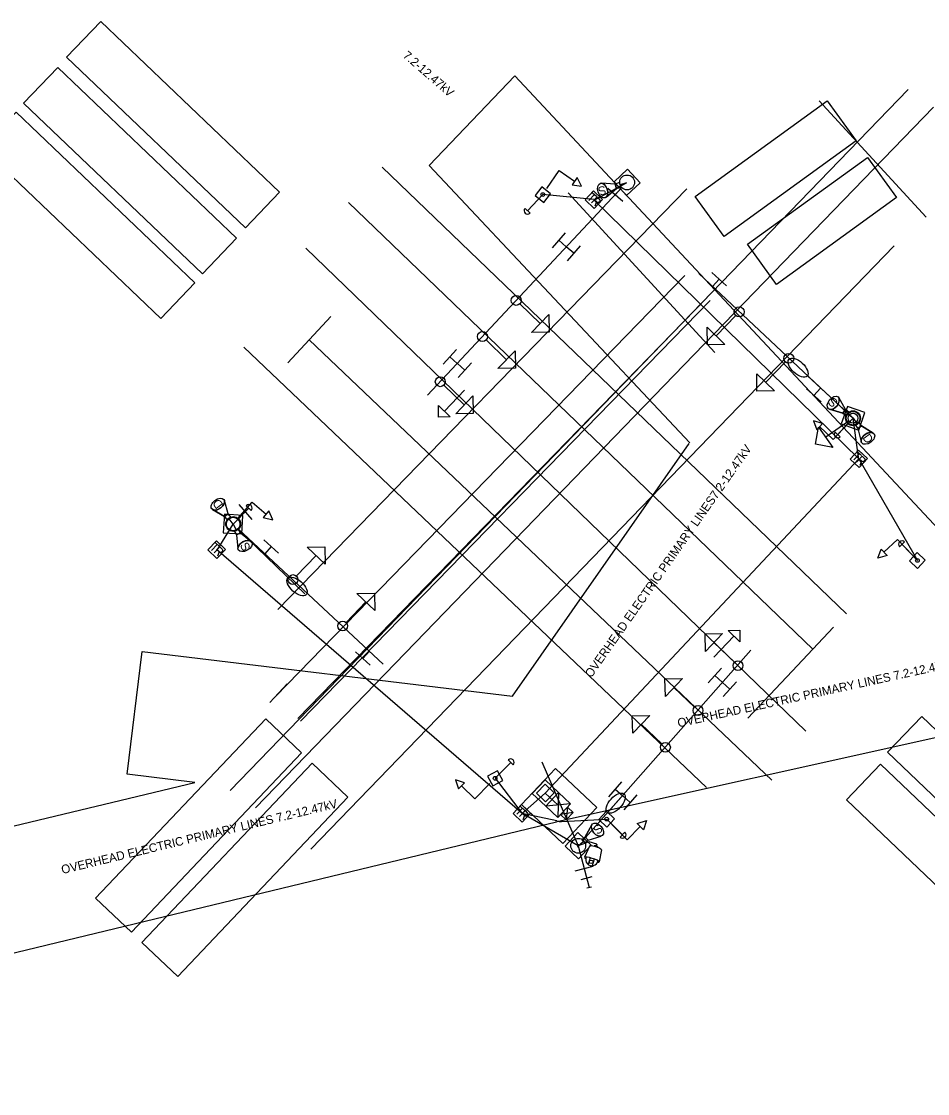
# Model space of a CAD drawing. Extents: x 1481246 to 1481610, y 378112 to 378300.
# Drawn here: x 1481367.5 to 1481514.1, y 378126.6 to 378300 of the extents above; entities that cross this region are included whole.
import ezdxf

# ---------------------------------------------------------------- set-up
doc = ezdxf.new("R2010")
doc.units = 0
for name, color, linetype in [('Default', 7, 'Continuous'), ('DR_X_Cells', 7, 'Continuous'), ('GK_Visualization', 7, 'Continuous'), ('PM_X_Cells', 7, 'Continuous'), ('RD_X_Cells', 7, 'Continuous'), ('SG_X_Poles', 7, 'Continuous'), ('SN_X_Private', 7, 'Continuous'), ('SV_X_Random_Point', 7, 'Continuous'), ('SV_X_Shot_Marker', 7, 'Continuous'), ('SV_X_Text_Elevation', 7, 'Continuous'), ('UT_X_Electric_Cells', 7, 'Continuous'), ('UT_X_Gas_Cells', 7, 'Continuous'), ('UT_X_Misc_Cells', 7, 'Continuous'), ('UT_X_Sanitary_Cells', 7, 'Continuous'), ('UT_X_Telecom_Cells', 7, 'Continuous'), ('UT_X_Unknown_Cells', 7, 'Continuous'), ('UT_X_Water_Cells', 7, 'Continuous')]:
    doc.layers.add(name, color=color, linetype=linetype)

msp = doc.modelspace()

# ---------------------------------------------------------------- linework, layer by layer
at = {"layer": 'Default'}
msp.add_line((1481410.48, 378192.83), (1481407.68, 378189.84), dxfattribs=at)
at = {"layer": 'GK_Visualization'}
for points in [[(1481465.41, 378271.81), (1481467.61, 378273.85), (1481465.57, 378276.05), (1481463.37, 378274.01)], [(1481451.99, 378270.7), (1481453.11, 378272.11), (1481451.7, 378273.23), (1481450.58, 378271.82)], [(1481500.13, 378234.89), (1481502.96, 378233.89), (1481503.96, 378236.72), (1481501.13, 378237.72)], [(1481400.14, 378217.29), (1481403.14, 378217.09), (1481403.33, 378220.09), (1481400.34, 378220.28)], [(1481512.5, 378211.52), (1481513.74, 378212.83), (1481512.44, 378214.07), (1481511.2, 378212.76)], [(1481443.78, 378176.34), (1481445.35, 378177.21), (1481444.49, 378178.79), (1481442.91, 378177.92)], [(1481462.22, 378169.69), (1481463.45, 378171), (1481462.14, 378172.24), (1481460.91, 378170.93)], [(1481457.64, 378164.54), (1481459.69, 378166.73), (1481457.5, 378168.78), (1481455.45, 378166.6)]]:
    msp.add_lwpolyline(points, close=True, dxfattribs=at)
for centre, radius in [((1481465.49, 378273.93), 1.2), ((1481451.84, 378271.97), 0.3), ((1481502.04, 378235.8), 1.2), ((1481401.74, 378218.69), 1.2), ((1481512.47, 378212.8), 0.3), ((1481444.13, 378177.57), 0.3), ((1481462.18, 378170.97), 0.3), ((1481457.57, 378166.66), 1.2)]:
    msp.add_circle(centre, radius, dxfattribs=at)
at = {"layer": 'PM_X_Cells'}
for p, q in [((1481464.77, 378270.86), (1481462.35, 378272.96)), ((1481463.56, 378271.91), (1481464.61, 378273.12)), ((1481453.39, 378263.37), (1481455.49, 378265.78)), ((1481454.44, 378264.58), (1481455.65, 378263.53)), ((1481456.86, 378262.48), (1481455.65, 378263.53)), ((1481457.91, 378263.68), (1481455.81, 378261.27)), ((1481479.19, 378259.36), (1481481.56, 378257.22)), ((1481480.37, 378258.29), (1481479.3, 378257.1)), ((1481435.72, 378244.55), (1481437.86, 378246.93)), ((1481436.79, 378245.74), (1481437.98, 378244.67)), ((1481439.22, 378243.55), (1481438.03, 378244.63)), ((1481440.29, 378244.74), (1481438.15, 378242.37)), ((1481496.91, 378238.43), (1481494.5, 378240.53)), ((1481495.71, 378239.48), (1481496.76, 378240.68)), ((1481402.68, 378221.85), (1481404.77, 378219.43)), ((1481403.73, 378220.64), (1481402.52, 378219.6)), ((1481406.72, 378216.11), (1481409.1, 378213.97)), ((1481407.91, 378215.04), (1481406.84, 378213.86)), ((1481423.91, 378195.89), (1481421.53, 378198.03)), ((1481422.72, 378196.96), (1481423.79, 378198.15)), ((1481478.62, 378193.01), (1481480.76, 378195.39)), ((1481479.69, 378194.2), (1481480.88, 378193.13)), ((1481482.11, 378191.98), (1481480.94, 378193.07)), ((1481483.2, 378193.15), (1481481.02, 378190.81)), ((1481462.51, 378174.58), (1481464.61, 378177)), ((1481463.56, 378175.79), (1481464.77, 378174.74)), ((1481465.99, 378173.68), (1481464.78, 378174.73)), ((1481467.04, 378174.89), (1481464.94, 378172.48))]:
    msp.add_line(p, q, dxfattribs=at)
at = {"layer": 'RD_X_Cells'}
for p, q in [((1481460.17, 378271.05), (1481465.38, 378273.87)), ((1481460.11, 378271.15), (1481451.84, 378271.97)), ((1481502.97, 378229.22), (1481460.09, 378271.13)), ((1481502.99, 378229.08), (1481502.04, 378235.8)), ((1481452.25, 378175.19), (1481502.99, 378229.24)), ((1481502.99, 378229.24), (1481512.47, 378212.8)), ((1481399.15, 378214.48), (1481401.74, 378218.69)), ((1481448.51, 378171.87), (1481399.06, 378214.55)), ((1481444.13, 378177.57), (1481448.52, 378171.87)), ((1481448.51, 378171.87), (1481452.25, 378175.19)), ((1481452.25, 378175.19), (1481454.31, 378173.24)), ((1481457.57, 378166.66), (1481448.45, 378171.91)), ((1481454.11, 378170.67), (1481448.52, 378171.87)), ((1481454.88, 378170.6), (1481462.18, 378170.97))]:
    msp.add_line(p, q, dxfattribs=at)
msp.add_arc((1481454.74, 378173.6), 3, 257.9002, 272.8324, dxfattribs=at)
at = {"layer": 'SG_X_Poles'}
for p, q in [((1481454.37, 378175.25), (1481454.25, 378171.24)), ((1481456.31, 378173.42), (1481452.31, 378173.07)), ((1481455.83, 378172.91), (1481455.63, 378170.88)), ((1481456.74, 378172.06), (1481454.72, 378171.74))]:
    msp.add_line(p, q, dxfattribs=at)
for points in [[(1481453.91, 378179.13), (1481448.41, 378173.32), (1481455.07, 378167.02), (1481460.57, 378172.83)], [(1481452.2, 378177.31), (1481450.13, 378175.13), (1481452.31, 378173.07), (1481454.37, 378175.25)], [(1481452.21, 378176.6), (1481450.84, 378175.15), (1481452.29, 378173.78), (1481453.67, 378175.23)], [(1481454.37, 378175.25), (1481456.31, 378173.42), (1481454.25, 378171.24), (1481452.31, 378173.07)], [(1481455.83, 378172.91), (1481456.74, 378172.06), (1481455.63, 378170.88), (1481454.72, 378171.74)]]:
    msp.add_lwpolyline(points, close=True, dxfattribs=at)
at = {"layer": 'SN_X_Private'}
for p, q in [((1481451.84, 378271.97), (1481451.84, 378271.97)), ((1481448.12, 378254.3), (1481451.43, 378251.11)), ((1481483.07, 378252.42), (1481479.87, 378249.12)), ((1481442.66, 378248.45), (1481445.97, 378245.26)), ((1481491.09, 378244.9), (1481487.89, 378241.6)), ((1481435.83, 378241.15), (1481439.14, 378237.96)), ((1481439.17, 378240.31), (1481435.91, 378236.93)), ((1481501.39, 378235.35), (1481497.62, 378232.72)), ((1481502.04, 378235.8), (1481502.04, 378235.8)), ((1481401.74, 378218.69), (1481401.74, 378218.69)), ((1481411.96, 378210.27), (1481415.16, 378213.58)), ((1481512.47, 378212.8), (1481512.47, 378212.8)), ((1481420.01, 378202.78), (1481423.21, 378206.08)), ((1481479.51, 378197.18), (1481482.77, 378200.56)), ((1481482.85, 378196.34), (1481479.54, 378199.54)), ((1481476.38, 378189.09), (1481473.04, 378192.26)), ((1481471.1, 378183.13), (1481467.77, 378186.3)), ((1481444.13, 378177.57), (1481444.13, 378177.57)), ((1481462.18, 378170.97), (1481462.18, 378170.97))]:
    msp.add_line(p, q, dxfattribs=at)
for points in [[(1481452.52, 378272.95), (1481454.51, 378275.84), (1481456.98, 378274.14)], [(1481501.22, 378234.93), (1481498.82, 378232.38), (1481496.64, 378234.44)], [(1481402.52, 378219.6), (1481404.8, 378222.25), (1481407.07, 378220.3)], [(1481511.64, 378213.66), (1481509.22, 378216.19), (1481507.05, 378214.12)], [(1481443.29, 378176.71), (1481440.83, 378174.23), (1481438.69, 378176.34)], [(1481463.03, 378170.12), (1481465.5, 378167.64), (1481467.62, 378169.76)]]:
    msp.add_lwpolyline(points, dxfattribs=at)
for points in [[(1481457.38, 378274.71), (1481456.58, 378273.56), (1481458.13, 378273.34)], [(1481452.82, 378252.55), (1481452.87, 378249.72), (1481450.04, 378249.67)], [(1481481.31, 378247.73), (1481478.48, 378247.68), (1481478.43, 378250.51)], [(1481447.35, 378246.71), (1481447.41, 378243.88), (1481444.58, 378243.82)], [(1481489.33, 378240.21), (1481486.5, 378240.16), (1481486.46, 378242.99)], [(1481440.53, 378239.41), (1481440.58, 378236.58), (1481437.76, 378236.53)], [(1481436.86, 378236.02), (1481434.98, 378235.98), (1481434.94, 378237.87)], [(1481496.16, 378233.93), (1481497.12, 378234.95), (1481495.62, 378235.4)], [(1481498.76, 378231.08), (1481495.98, 378231.58), (1481496.47, 378234.36)], [(1481407.53, 378220.83), (1481406.62, 378219.76), (1481408.14, 378219.38)], [(1481413.73, 378214.97), (1481416.55, 378215.01), (1481416.6, 378212.18)], [(1481506.57, 378214.63), (1481507.54, 378213.62), (1481506.04, 378213.16)], [(1481421.77, 378207.47), (1481424.6, 378207.51), (1481424.64, 378204.69)], [(1481478.15, 378198.09), (1481478.1, 378200.91), (1481480.93, 378200.96)], [(1481481.82, 378201.47), (1481483.71, 378201.5), (1481483.74, 378199.62)], [(1481471.67, 378190.81), (1481471.6, 378193.64), (1481474.43, 378193.71)], [(1481466.39, 378184.85), (1481466.32, 378187.68), (1481469.15, 378187.75)], [(1481438.2, 378175.84), (1481439.19, 378176.83), (1481437.7, 378177.32)], [(1481468.12, 378169.26), (1481467.13, 378170.25), (1481468.61, 378170.75)]]:
    msp.add_lwpolyline(points, close=True, dxfattribs=at)
for centre in [(1481447.54, 378254.85), (1481483.62, 378253), (1481442.08, 378249.01), (1481491.65, 378245.48), (1481435.25, 378241.7), (1481502.04, 378235.8), (1481411.41, 378209.7), (1481419.45, 378202.2), (1481483.42, 378195.79), (1481476.96, 378188.54), (1481471.68, 378182.58)]:
    msp.add_circle(centre, 0.8, dxfattribs=at)
at = {"layer": 'SV_X_Random_Point'}
for p, q in [((1481464.61, 378273.12), (1481433.2, 378239.51)), ((1481501.16, 378236.62), (1481477.09, 378259.19)), ((1481402.61, 378217.86), (1481426.02, 378196.05)), ((1481458.38, 378167.55), (1481485.49, 378198.31))]:
    msp.add_line(p, q, dxfattribs=at)
at = {"layer": 'SV_X_Shot_Marker'}
for p, q in [((1481460.11, 378271.15), (1481460.11, 378271.15)), ((1481502.99, 378229.24), (1481502.99, 378229.24)), ((1481399.06, 378214.55), (1481399.06, 378214.55)), ((1481448.45, 378171.91), (1481448.45, 378171.91))]:
    msp.add_line(p, q, dxfattribs=at)
for points in [[(1481460.07, 378272.56), (1481461.52, 378271.19), (1481460.15, 378269.74), (1481458.7, 378271.11)], [(1481502.95, 378230.65), (1481504.4, 378229.28), (1481503.03, 378227.83), (1481501.58, 378229.2)], [(1481399.03, 378215.97), (1481400.48, 378214.59), (1481399.1, 378213.14), (1481397.65, 378214.52)], [(1481448.41, 378173.32), (1481449.87, 378171.94), (1481448.49, 378170.49), (1481447.04, 378171.87)]]:
    msp.add_lwpolyline(points, close=True, dxfattribs=at)
for points in [[(1481460.22, 378271.97), (1481459.3, 378271)], [(1481459.71, 378270.61), (1481460.62, 378271.58), (1481460.99, 378271.24), (1481461.02, 378271.19), (1481461.06, 378271.13), (1481461.07, 378271.09), (1481461.08, 378271.05), (1481461.07, 378270.99), (1481461.06, 378270.93), (1481461.01, 378270.85), (1481460.93, 378270.76), (1481460.89, 378270.74), (1481460.83, 378270.7), (1481460.75, 378270.68), (1481460.7, 378270.69), (1481460.66, 378270.69), (1481460.64, 378270.7), (1481460.61, 378270.71), (1481460.53, 378270.77), (1481460.18, 378271.11)], [(1481459.91, 378272.26), (1481460.52, 378271.69)], [(1481460.53, 378270.77), (1481460.28, 378270.07)], [(1481503.1, 378230.06), (1481502.18, 378229.09)], [(1481502.59, 378228.71), (1481503.5, 378229.67), (1481503.87, 378229.33), (1481503.9, 378229.28), (1481503.94, 378229.22), (1481503.95, 378229.18), (1481503.95, 378229.14), (1481503.95, 378229.08), (1481503.94, 378229.02), (1481503.89, 378228.94), (1481503.81, 378228.85), (1481503.77, 378228.83), (1481503.71, 378228.8), (1481503.63, 378228.77), (1481503.58, 378228.78), (1481503.54, 378228.78), (1481503.52, 378228.79), (1481503.49, 378228.8), (1481503.41, 378228.86), (1481503.06, 378229.2)], [(1481502.79, 378230.35), (1481503.39, 378229.78)], [(1481503.41, 378228.86), (1481503.16, 378228.16)], [(1481398.87, 378215.66), (1481399.47, 378215.09)], [(1481399.17, 378215.37), (1481398.25, 378214.4)], [(1481398.66, 378214.02), (1481399.58, 378214.99), (1481399.94, 378214.64), (1481399.97, 378214.6), (1481400.01, 378214.53), (1481400.02, 378214.49), (1481400.03, 378214.46), (1481400.02, 378214.39), (1481400.01, 378214.33), (1481399.97, 378214.26), (1481399.88, 378214.16), (1481399.84, 378214.14), (1481399.79, 378214.11), (1481399.7, 378214.09), (1481399.65, 378214.09), (1481399.62, 378214.1), (1481399.59, 378214.1), (1481399.56, 378214.12), (1481399.49, 378214.18), (1481399.13, 378214.51)], [(1481399.49, 378214.18), (1481399.23, 378213.48)], [(1481448.56, 378172.72), (1481447.64, 378171.75)], [(1481448.05, 378171.37), (1481448.97, 378172.34), (1481449.33, 378171.99), (1481449.36, 378171.95), (1481449.4, 378171.88), (1481449.41, 378171.85), (1481449.42, 378171.81), (1481449.41, 378171.74), (1481449.4, 378171.68), (1481449.36, 378171.61), (1481449.27, 378171.51), (1481449.23, 378171.49), (1481449.17, 378171.46), (1481449.09, 378171.44), (1481449.04, 378171.44), (1481449, 378171.45), (1481448.98, 378171.45), (1481448.95, 378171.47), (1481448.88, 378171.53), (1481448.52, 378171.87)], [(1481448.25, 378173.01), (1481448.86, 378172.44)], [(1481448.88, 378171.53), (1481448.62, 378170.83)]]:
    msp.add_lwpolyline(points, dxfattribs=at)
at = {"layer": 'SV_X_Text_Elevation'}
for p, q in [((1481496.55, 378287.15), (1481513.86, 378268.32)), ((1481455.93, 378272.24), (1481479.67, 378246.4))]:
    msp.add_line(p, q, dxfattribs=at)
at = {"layer": 'UT_X_Electric_Cells'}
for p, q in [((1481463.55, 378273.67), (1481461.34, 378273.82)), ((1481463.55, 378273.67), (1481461.34, 378273.82)), ((1481463.79, 378272.96), (1481462.08, 378271.54)), ((1481462.08, 378271.54), (1481463.79, 378272.96)), ((1481463.79, 378272.96), (1481463.55, 378273.67)), ((1481465.39, 378273.87), (1481464.38, 378273.55)), ((1481451.84, 378271.97), (1481449.37, 378269.35)), ((1481449.78, 378268.96), (1481448.97, 378269.73)), ((1481500.85, 378237.21), (1481499.74, 378239.13)), ((1481500.85, 378237.21), (1481499.74, 378239.13)), ((1481500.39, 378236.62), (1481498.26, 378237.24)), ((1481498.26, 378237.24), (1481500.39, 378236.62)), ((1481500.39, 378236.62), (1481500.85, 378237.21)), ((1481502.04, 378235.8), (1481501.21, 378236.46)), ((1481502.04, 378235.8), (1481499.57, 378233.19)), ((1481502.04, 378235.8), (1481502.67, 378234.95)), ((1481503.42, 378234.57), (1481502.82, 378234.12)), ((1481502.82, 378234.12), (1481503.42, 378234.57)), ((1481503.42, 378234.57), (1481505.31, 378233.4)), ((1481505.31, 378233.4), (1481503.42, 378234.57)), ((1481499.98, 378232.8), (1481499.17, 378233.57)), ((1481502.82, 378234.12), (1481503.37, 378231.98)), ((1481502.82, 378234.12), (1481503.37, 378231.98)), ((1481400.93, 378220.35), (1481400.33, 378222.49)), ((1481400.93, 378220.35), (1481400.33, 378222.49)), ((1481400.33, 378219.89), (1481398.42, 378221.02)), ((1481398.42, 378221.02), (1481400.33, 378219.89)), ((1481401.74, 378218.69), (1481404.26, 378221.26)), ((1481403.86, 378221.65), (1481404.66, 378220.86)), ((1481400.33, 378219.89), (1481400.93, 378220.35)), ((1481400.93, 378220.35), (1481400.33, 378219.89)), ((1481401.74, 378218.69), (1481401.09, 378219.53)), ((1481401.74, 378218.69), (1481402.24, 378217.75)), ((1481402.92, 378217.27), (1481402.26, 378216.92)), ((1481402.92, 378217.27), (1481404.63, 378215.85)), ((1481404.63, 378215.85), (1481402.92, 378217.27)), ((1481402.26, 378216.92), (1481402.51, 378214.71)), ((1481402.26, 378216.92), (1481402.51, 378214.71)), ((1481509.58, 378215.01), (1481510.39, 378215.79)), ((1481512.47, 378212.8), (1481509.98, 378215.4)), ((1481444.13, 378177.57), (1481446.65, 378180.14)), ((1481446.25, 378180.53), (1481447.05, 378179.74)), ((1481462.18, 378170.97), (1481464.75, 378168.44)), ((1481458.72, 378168.11), (1481459.76, 378170.07)), ((1481459.76, 378170.07), (1481458.72, 378168.11)), ((1481465.14, 378168.84), (1481464.36, 378168.04)), ((1481457.57, 378166.66), (1481458.38, 378167.35)), ((1481458.72, 378168.11), (1481459.2, 378167.54)), ((1481459.2, 378167.54), (1481461.31, 378168.22)), ((1481459.2, 378167.54), (1481461.31, 378168.22)), ((1481457.49, 378166.43), (1481457.64, 378166.9)), ((1481459.41, 378166.59), (1481458.59, 378164.8)), ((1481460.56, 378166.91), (1481460.49, 378166.67)), ((1481461.32, 378165.99), (1481460.97, 378164.05)), ((1481459.51, 378164.71), (1481459.17, 378163.64)), ((1481460.17, 378164.5), (1481459.84, 378163.43))]:
    msp.add_line(p, q, dxfattribs=at)
for points in [[(1481409.25, 378272.36), (1481403.73, 378266.57), (1481374.78, 378294.17), (1481380.3, 378299.96)], [(1481402.3, 378264.92), (1481396.77, 378259.13), (1481367.83, 378286.73), (1481373.35, 378292.52)], [(1481481.2, 378265.18), (1481476.51, 378271.66), (1481497.85, 378287.12), (1481502.54, 378280.64)], [(1481395.54, 378257.69), (1481390.02, 378251.9), (1481361.07, 378279.5), (1481366.6, 378285.29)], [(1481489.66, 378257.44), (1481484.96, 378263.92), (1481504.37, 378277.97), (1481509.06, 378271.49)], [(1481464.5, 378273.19), (1481464.27, 378273.9), (1481463.55, 378273.67), (1481463.79, 378272.96)], [(1481500.98, 378236.16), (1481501.44, 378236.75), (1481500.85, 378237.21), (1481500.39, 378236.62)], [(1481502.98, 378235.17), (1481502.37, 378234.73), (1481502.82, 378234.12), (1481503.42, 378234.57)], [(1481400.79, 378219.3), (1481401.39, 378219.76), (1481400.93, 378220.35), (1481400.33, 378219.89)], [(1481402.57, 378217.93), (1481401.91, 378217.58), (1481402.26, 378216.92), (1481402.92, 378217.27)], [(1481385.28, 378152.69), (1481379.48, 378158.2), (1481407.02, 378187.21), (1481412.82, 378181.7)], [(1481542.1, 378159.96), (1481536.58, 378154.17), (1481507.63, 378181.78), (1481513.16, 378187.57)], [(1481392.78, 378145.5), (1481386.98, 378151), (1481414.52, 378180.01), (1481420.32, 378174.5)], [(1481535.46, 378152.26), (1481529.94, 378146.47), (1481500.99, 378174.07), (1481506.51, 378179.86)], [(1481458.14, 378167.63), (1481458.62, 378167.06), (1481459.2, 378167.54), (1481458.72, 378168.11)]]:
    msp.add_lwpolyline(points, close=True, dxfattribs=at)
for points in [[(1481464.5, 378273.19), (1481464.27, 378273.9), (1481463.55, 378273.67), (1481463.79, 378272.96), (1481464.5, 378273.19)], [(1481500.98, 378236.16), (1481501.44, 378236.75), (1481500.85, 378237.21), (1481500.39, 378236.62), (1481500.98, 378236.16)], [(1481503.42, 378234.57), (1481502.98, 378235.17), (1481502.37, 378234.73), (1481502.82, 378234.12)], [(1481400.33, 378219.89), (1481400.79, 378219.3), (1481401.39, 378219.76), (1481400.93, 378220.35)], [(1481402.57, 378217.93), (1481401.91, 378217.58), (1481402.26, 378216.92), (1481402.92, 378217.27), (1481402.57, 378217.93)], [(1481460.56, 378166.91), (1481459.37, 378167.28), (1481457.57, 378166.66)], [(1481458.14, 378167.63), (1481458.62, 378167.06), (1481459.2, 378167.54), (1481458.72, 378168.11), (1481458.14, 378167.63)], [(1481460.19, 378166.55), (1481460.25, 378166.74), (1481460.72, 378166.59), (1481460.66, 378166.4)]]:
    msp.add_lwpolyline(points, dxfattribs=at)
msp.add_circle((1481459.67, 378164.06), 0.273, dxfattribs=at)
for centre, radius, start, end in [((1481449.37, 378269.35), 0.56, 136.6662, 316.6659), ((1481499.57, 378233.19), 0.56, 136.6662, 316.6659), ((1481404.26, 378221.26), 0.56, 315.5351, 135.5347), ((1481509.98, 378215.4), 0.56, 43.6893, 223.6889), ((1481446.65, 378180.14), 0.56, 315.5351, 135.5347), ((1481464.75, 378168.44), 0.56, 225.5351, 45.5347), ((1481459.78, 378164.43), 1, 155.5912, 349.5562)]:
    msp.add_arc(centre, radius, start, end, dxfattribs=at)
for centre, major_axis in [((1481461.54, 378272.62), (-0.38, 1.18)), ((1481498.85, 378238.3), (0.763, 0.976)), ((1481504.45, 378232.54), (-0.998, -0.734)), ((1481399.26, 378221.9), (0.983, 0.755)), ((1481403.66, 378215.12), (-1.09, -0.59)), ((1481460.68, 378169.27), (0.795, -0.951))]:
    msp.add_ellipse(centre, major_axis=major_axis, ratio=0.621318, dxfattribs=at)
for centre, major_axis, ratio, start_param, end_param in [((1481461.54, 378272.62), (-0.38, 1.18), 0.621318, 3.386213, 6.038231), ((1481498.85, 378238.3), (0.763, 0.976), 0.621318, 3.386213, 6.038231), ((1481504.45, 378232.54), (-0.998, -0.734), 0.621318, 3.386213, 6.038231), ((1481399.26, 378221.9), (0.983, 0.755), 0.621318, 3.386213, 6.038231), ((1481403.66, 378215.12), (-1.09, -0.59), 0.621318, 3.386213, 6.038231), ((1481460.68, 378169.27), (0.795, -0.951), 0.621318, 3.386213, 6.038231), ((1481460.37, 378166.29), (0.954, -0.299), 0.2, 0, 3.141593), ((1481459.78, 378164.43), (1.19, -0.37), 0.16, 5.62986, 10.078104)]:
    msp.add_ellipse(centre, major_axis=major_axis, ratio=ratio, start_param=start_param, end_param=end_param, dxfattribs=at)
at = {"layer": 'UT_X_Gas_Cells'}
for p, q in [((1481457.57, 378166.66), (1481459.34, 378159.89)), ((1481457.08, 378162.61), (1481459.98, 378163.37)), ((1481458.07, 378161.21), (1481459.81, 378161.67)), ((1481459.73, 378159.99), (1481458.96, 378159.79))]:
    msp.add_line(p, q, dxfattribs=at)
at = {"layer": 'UT_X_Misc_Cells'}
for p, q in [((1481401.28, 378175.62), (1481510.99, 378288.96)), ((1481405.34, 378172.78), (1481515.04, 378286.12)), ((1481500.97, 378204.18), (1481425.86, 378276.4)), ((1481475.17, 378272.91), (1481408.94, 378204.85)), ((1481495.53, 378198.45), (1481420.42, 378270.67)), ((1481494.42, 378185.17), (1481413.48, 378263.3)), ((1481414.28, 378166.12), (1481508.71, 378263.68)), ((1481474.82, 378258.87), (1481408.59, 378190.81)), ((1481478.42, 378255.32), (1481412.19, 378187.26)), ((1481478.9, 378254.85), (1481412.66, 378186.79)), ((1481410.56, 378244.78), (1481417.55, 378252.23)), ((1481488.91, 378177.28), (1481414.05, 378248.5)), ((1481478.35, 378176.06), (1481403.49, 378247.28)), ((1481492.17, 378194.88), (1481498.89, 378202.02)), ((1481492.17, 378194.88), (1481485.02, 378187.3))]:
    msp.add_line(p, q, dxfattribs=at)
at = {"layer": 'UT_X_Sanitary_Cells'}
msp.add_line((1481501.99, 378235.85), (1481494.65, 378242.64), dxfattribs=at)
msp.add_ellipse((1481493.15, 378243.96), major_axis=(-1.47, 1.36), ratio=0.5, dxfattribs=at)
at = {"layer": 'UT_X_Telecom_Cells'}
msp.add_line((1481451.71, 378180.23), (1481457.57, 378166.66), dxfattribs=at)
at = {"layer": 'UT_X_Unknown_Cells'}
for p, q in [((1481402.54, 378217.79), (1481413.36, 378207.41)), ((1481458.38, 378167.55), (1481464.97, 378175.03))]:
    msp.add_line(p, q, dxfattribs=at)
for centre in [(1481502.05, 378235.8), (1481401.74, 378218.69)]:
    msp.add_circle(centre, 1.1, dxfattribs=at)
for centre, major_axis in [((1481412.08, 378208.59), (1.49, -1.34)), ((1481463.63, 378173.55), (1.34, 1.49))]:
    msp.add_ellipse(centre, major_axis=major_axis, ratio=0.5, dxfattribs=at)
at = {"layer": 'UT_X_Water_Cells'}
for p, q in [((1481433.47, 378276.68), (1481447.29, 378291.19)), ((1481475.65, 378231.83), (1481433.47, 378276.68)), ((1481446.96, 378190.87), (1481475.55, 378231.69)), ((1481384.61, 378178.23), (1481387, 378198.08)), ((1481387, 378198.08), (1481446.96, 378190.87)), ((1481519.61, 378185.08), (1481453.89, 378170.46)), ((1481395.55, 378176.91), (1481384.61, 378178.23)), ((1481336.96, 378162.81), (1481395.55, 378176.91)), ((1481454.06, 378170.5), (1481341.66, 378143.37))]:
    msp.add_line(p, q, dxfattribs=at)
msp.add_lwpolyline([(1481447.29, 378291.19), (1481529.73, 378203.04), (1481610.32, 378126.59)], dxfattribs=at)

# ---------------------------------------------------------------- texts
at = {"layer": 'DR_X_Cells'}
for s, rotation, p in [('7.2-12.47kV', 319.0221, (1481429.09, 378294.27)), ('OVERHEAD ELECTRIC PRIMARY LINES7.2-12.47kV', 54.9948, (1481459.69, 378193.72)), ('OVERHEAD ELECTRIC PRIMARY LINES 7.2-12.47kV', 12.3397, (1481473.8, 378185.8)), ('OVERHEAD ELECTRIC PRIMARY LINES 7.2-12.47kV', 13.5718, (1481374.11, 378162.08))]:
    msp.add_text(s, height=1.4, rotation=rotation, dxfattribs=at).set_placement(p)
at = {"layer": 'UT_X_Electric_Cells'}
for s, rotation, p in [('S', 197.9843, (1481461.84, 378273.46)), ('S', 141.9997, (1481499.71, 378238.52)), ('D', 306.3586, (1481503.51, 378232.63)), ('D', 127.5704, (1481400.2, 378221.83)), ('S', 298.2962, (1481402.78, 378215.27)), ('S', 39.9413, (1481460.71, 378168.38))]:
    msp.add_text(s, height=1.4, rotation=rotation, dxfattribs=at).set_placement(p)

doc.saveas('drawing.dxf')
